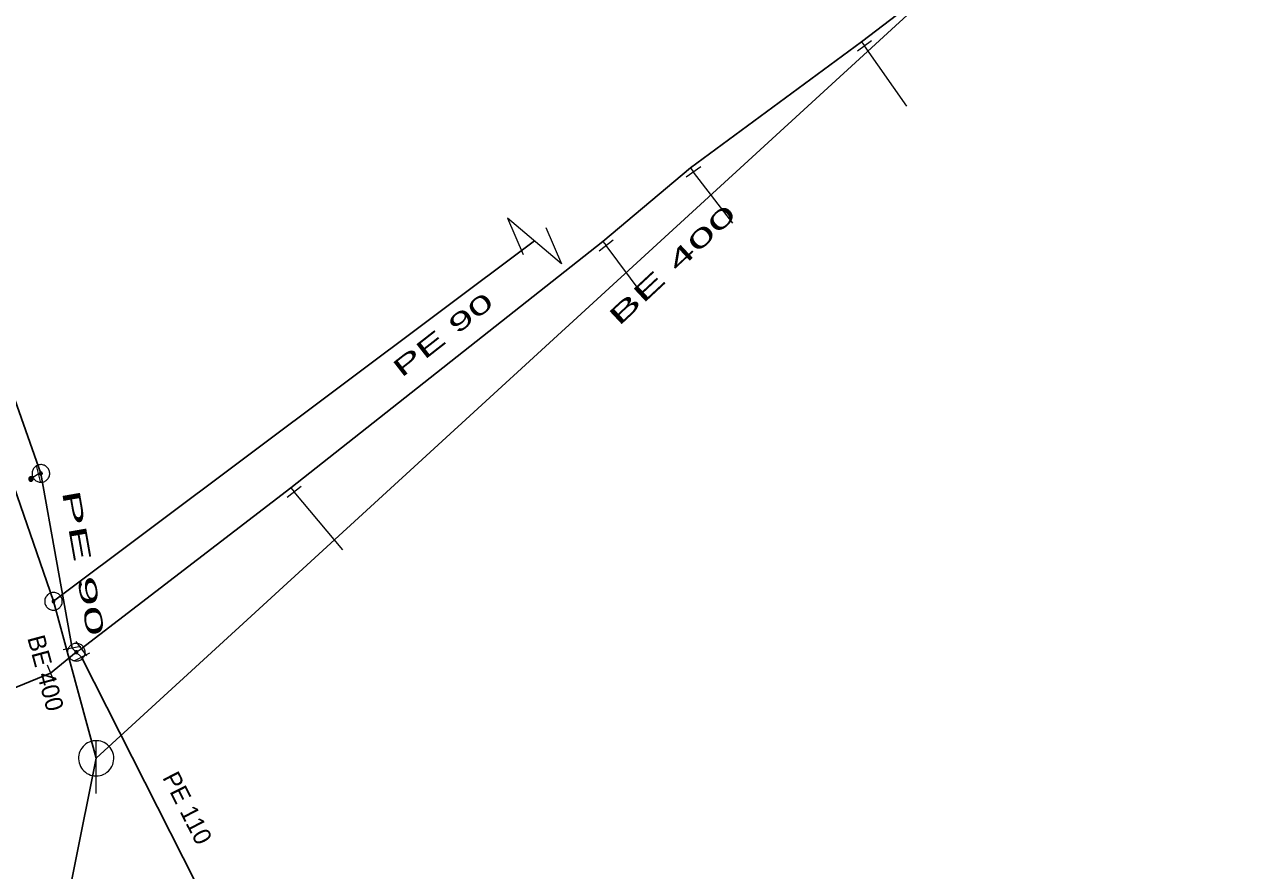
# Model space of a CAD drawing. Extents: x -779496 to -779026, y -977086 to -976624.
# Drawn here: x -779435.1 to -779365.5, y -977014.1 to -976966.2 of the extents above; entities that cross this region are included whole.
import ezdxf

# ---------------------------------------------------------------- set-up
doc = ezdxf.new("R2010")
doc.units = 0
doc.header["$LTSCALE"] = 0.4
doc.linetypes.add('MEDIUM_DASHED', pattern=[4.5, 3, -1.5])
for name, color, linetype, lineweight in [('1', 7, 'MEDIUM_DASHED', 25), ('13', 7, 'Continuous', 13), ('14', 7, 'Continuous', 13), ('17', 7, 'Continuous', 25), ('22', 7, 'Continuous', 13), ('31', 7, 'Continuous', 13), ('34', 7, 'Continuous', 13), ('47', 7, 'Continuous', 13), ('9', 7, 'Continuous', 13)]:
    doc.layers.add(name, color=color, linetype=linetype, lineweight=lineweight)

msp = doc.modelspace()

# ---------------------------------------------------------------- linework, layer by layer
at = {"layer": '13'}
for p, q in [((-779385.116, -976970.776), (-779387.52, -976967.366)), ((-779394.986, -976977.408), (-779397.208, -976974.51)), ((-779400.116, -976981.414), (-779402.155, -976978.679)), ((-779417.083, -976995.903), (-779419.831, -976992.633))]:
    msp.add_line(p, q, dxfattribs=at)
at = {"layer": '14', "lineweight": 25}
for p, q in [((-779370.105, -976951.862), (-779431.048, -977007.721)), ((-779406.215, -976978.414), (-779433.467, -976998.827))]:
    msp.add_line(p, q, dxfattribs=at)
at = {"layer": '14'}
for p, q in [((-779387.699, -976967.124), (-779387.52, -976967.366)), ((-779397.383, -976974.263), (-779397.208, -976974.51)), ((-779402.342, -976978.442), (-779402.155, -976978.679)), ((-779434.328, -976991.62), (-779434.743, -976991.897)), ((-779434.181, -976991.585), (-779434.328, -976991.62)), ((-779420.017, -976992.39), (-779419.831, -976992.633)), ((-779432.419, -977001.481), (-779432.174, -977001.71)), ((-779432.174, -977001.71), (-779431.903, -977001.512)), ((-779432.174, -977001.71), (-779431.872, -977001.993))]:
    msp.add_line(p, q, dxfattribs=at)
at = {"layer": '14', "lineweight": 25}
for points in [[(-779436.28, -976990.67), (-779433.467, -976998.827), (-779431.048, -977007.721)], [(-779431.048, -977007.721), (-779433.53, -977020.039), (-779409.204, -977061.045)]]:
    msp.add_lwpolyline(points, dxfattribs=at)
at = {"layer": '17'}
for p, q in [((-779434.181, -976991.585), (-779432.419, -977001.481)), ((-779432.174, -977001.71), (-779433.636, -977002.894))]:
    msp.add_line(p, q, dxfattribs=at)
for points in [[(-779454.175, -976923.809), (-779450.772, -976938.068), (-779448.031, -976948.717), (-779444.473, -976962.508), (-779436.901, -976983.894), (-779434.181, -976991.585)], [(-779433.636, -977002.894), (-779441.438, -977006.098), (-779447.947, -976991.515), (-779454.579, -976971.633), (-779460.072, -976955.085), (-779464.768, -976941.099)], [(-779431.903, -977001.512), (-779420.017, -976992.39), (-779402.342, -976978.442), (-779397.383, -976974.263), (-779387.699, -976967.124), (-779382.057, -976962.824), (-779375.728, -976957.945), (-779374.629, -976957.155), (-779365.489, -976951.461)], [(-779431.872, -977001.993), (-779421.818, -977021.866), (-779420.403, -977025.364), (-779413.614, -977038.243), (-779404.897, -977052.484), (-779402.2, -977057.302)]]:
    msp.add_lwpolyline(points, dxfattribs=at)
at = {"layer": '22'}
msp.add_line((-779431.048, -977009.721), (-779431.047, -977006.721), dxfattribs=at)
msp.add_lwpolyline([(-779430.048, -977007.721), (-779430.053, -977007.612), (-779430.071, -977007.504), (-779430.101, -977007.398), (-779430.141, -977007.297), (-779430.193, -977007.2), (-779430.255, -977007.11), (-779430.327, -977007.027), (-779430.407, -977006.953), (-779430.495, -977006.887), (-779430.589, -977006.832), (-779430.689, -977006.787), (-779430.794, -977006.754), (-779430.901, -977006.732), (-779431.01, -977006.722), (-779431.12, -977006.724), (-779431.228, -977006.738), (-779431.335, -977006.763), (-779431.438, -977006.8), (-779431.536, -977006.849), (-779431.628, -977006.907), (-779431.714, -977006.976), (-779431.791, -977007.053), (-779431.86, -977007.139), (-779431.919, -977007.231), (-779431.967, -977007.329), (-779432.004, -977007.432), (-779432.03, -977007.539), (-779432.044, -977007.647), (-779432.047, -977007.757), (-779432.037, -977007.866), (-779432.016, -977007.973), (-779431.982, -977008.077), (-779431.938, -977008.177), (-779431.883, -977008.272), (-779431.817, -977008.36), (-779431.743, -977008.44), (-779431.66, -977008.512), (-779431.57, -977008.574), (-779431.474, -977008.626), (-779431.372, -977008.667), (-779431.267, -977008.697), (-779431.159, -977008.715), (-779431.049, -977008.721), (-779430.94, -977008.715), (-779430.832, -977008.697), (-779430.727, -977008.668), (-779430.625, -977008.627), (-779430.528, -977008.575), (-779430.438, -977008.513), (-779430.355, -977008.442), (-779430.28, -977008.362), (-779430.215, -977008.274), (-779430.159, -977008.18), (-779430.115, -977008.08), (-779430.081, -977007.976), (-779430.059, -977007.868), (-779430.049, -977007.759)], close=True, dxfattribs=at)
at = {"layer": '31'}
msp.add_lwpolyline([(-779405.568, -976977.65), (-779404.689, -976979.706), (-779407.741, -976977.12), (-779406.861, -976979.176)], dxfattribs=at)
for points in [[(-779433.292, -976999.295), (-779433.244, -976999.274), (-779433.198, -976999.248), (-779433.156, -976999.218), (-779433.117, -976999.184), (-779433.081, -976999.145), (-779433.05, -976999.102), (-779433.024, -976999.058), (-779433.002, -976999.01), (-779432.985, -976998.961), (-779432.973, -976998.91), (-779432.967, -976998.857), (-779432.968, -976998.805), (-779432.972, -976998.753), (-779432.983, -976998.702), (-779432.998, -976998.652), (-779433.019, -976998.604), (-779433.045, -976998.558), (-779433.075, -976998.515), (-779433.109, -976998.477), (-779433.148, -976998.441), (-779433.191, -976998.41), (-779433.236, -976998.383), (-779433.283, -976998.361), (-779433.332, -976998.344), (-779433.383, -976998.333), (-779433.436, -976998.327), (-779433.488, -976998.327), (-779433.54, -976998.332), (-779433.591, -976998.343), (-779433.641, -976998.358), (-779433.689, -976998.379), (-779433.735, -976998.405), (-779433.778, -976998.435), (-779433.816, -976998.469), (-779433.852, -976998.508), (-779433.883, -976998.55), (-779433.91, -976998.595), (-779433.932, -976998.642), (-779433.949, -976998.692), (-779433.96, -976998.743), (-779433.966, -976998.796), (-779433.967, -976998.847), (-779433.961, -976998.9), (-779433.95, -976998.951), (-779433.935, -976999.001), (-779433.914, -976999.049), (-779433.888, -976999.095), (-779433.859, -976999.137), (-779433.824, -976999.176), (-779433.785, -976999.212), (-779433.743, -976999.243), (-779433.699, -976999.269), (-779433.651, -976999.291), (-779433.601, -976999.308), (-779433.55, -976999.32), (-779433.497, -976999.326), (-779433.446, -976999.326), (-779433.393, -976999.321), (-779433.342, -976999.31)], [(-779433.438, -976998.903), (-779433.429, -976998.9), (-779433.423, -976998.896), (-779433.416, -976998.891), (-779433.409, -976998.885), (-779433.403, -976998.879), (-779433.398, -976998.872), (-779433.394, -976998.864), (-779433.39, -976998.857), (-779433.388, -976998.848), (-779433.386, -976998.84), (-779433.385, -976998.831), (-779433.385, -976998.823), (-779433.386, -976998.815), (-779433.387, -976998.806), (-779433.39, -976998.798), (-779433.393, -976998.789), (-779433.397, -976998.783), (-779433.402, -976998.776), (-779433.408, -976998.769), (-779433.414, -976998.763), (-779433.421, -976998.758), (-779433.429, -976998.754), (-779433.436, -976998.75), (-779433.445, -976998.747), (-779433.453, -976998.746), (-779433.462, -976998.745), (-779433.47, -976998.745), (-779433.478, -976998.746), (-779433.487, -976998.747), (-779433.495, -976998.75), (-779433.504, -976998.753), (-779433.51, -976998.757), (-779433.517, -976998.762), (-779433.524, -976998.768), (-779433.53, -976998.774), (-779433.535, -976998.78), (-779433.539, -976998.789), (-779433.543, -976998.796), (-779433.546, -976998.805), (-779433.547, -976998.813), (-779433.548, -976998.822), (-779433.548, -976998.83), (-779433.547, -976998.838), (-779433.546, -976998.847), (-779433.543, -976998.855), (-779433.54, -976998.864), (-779433.536, -976998.87), (-779433.531, -976998.877), (-779433.525, -976998.884), (-779433.519, -976998.89), (-779433.513, -976998.895), (-779433.504, -976998.899), (-779433.497, -976998.903), (-779433.488, -976998.905), (-779433.48, -976998.907), (-779433.471, -976998.908), (-779433.463, -976998.908), (-779433.455, -976998.907), (-779433.446, -976998.906)]]:
    msp.add_lwpolyline(points, close=True, dxfattribs=at)
at = {"layer": '34'}
for p, q in [((-779387.117, -976967.069), (-779387.923, -976967.661)), ((-779396.798, -976974.222), (-779397.617, -976974.796)), ((-779401.762, -976978.368), (-779402.547, -976978.988)), ((-779434.444, -976991.133), (-779434.212, -976992.106)), ((-779419.435, -976992.327), (-779420.227, -976992.937)), ((-779431.926, -977001.392), (-779432.911, -977001.568)), ((-779432.199, -977001.109), (-779431.607, -977001.915)), ((-779431.426, -977001.766), (-779432.318, -977002.218)), ((-779433.826, -977002.431), (-779433.446, -977003.356))]:
    msp.add_line(p, q, dxfattribs=at)
at = {"layer": '47'}
for points in [[(-779434.065, -976992.071), (-779434.015, -976992.056), (-779433.966, -976992.036), (-779433.921, -976992.011), (-779433.877, -976991.982), (-779433.837, -976991.948), (-779433.801, -976991.909), (-779433.77, -976991.868), (-779433.742, -976991.823), (-779433.719, -976991.777), (-779433.701, -976991.727), (-779433.689, -976991.676), (-779433.683, -976991.624), (-779433.681, -976991.572), (-779433.685, -976991.52), (-779433.694, -976991.469), (-779433.709, -976991.419), (-779433.729, -976991.37), (-779433.754, -976991.324), (-779433.783, -976991.281), (-779433.817, -976991.241), (-779433.856, -976991.205), (-779433.897, -976991.173), (-779433.942, -976991.145), (-779433.988, -976991.122), (-779434.038, -976991.105), (-779434.089, -976991.093), (-779434.141, -976991.086), (-779434.193, -976991.085), (-779434.245, -976991.089), (-779434.296, -976991.098), (-779434.346, -976991.113), (-779434.395, -976991.133), (-779434.442, -976991.157), (-779434.484, -976991.187), (-779434.524, -976991.221), (-779434.56, -976991.259), (-779434.593, -976991.3), (-779434.62, -976991.345), (-779434.643, -976991.392), (-779434.66, -976991.442), (-779434.672, -976991.493), (-779434.679, -976991.544), (-779434.68, -976991.597), (-779434.676, -976991.649), (-779434.667, -976991.7), (-779434.652, -976991.75), (-779434.632, -976991.799), (-779434.608, -976991.845), (-779434.578, -976991.888), (-779434.544, -976991.928), (-779434.506, -976991.964), (-779434.465, -976991.996), (-779434.42, -976992.023), (-779434.373, -976992.046), (-779434.323, -976992.064), (-779434.272, -976992.076), (-779434.221, -976992.082), (-779434.168, -976992.084), (-779434.116, -976992.08)], [(-779434.161, -976991.664), (-779434.153, -976991.662), (-779434.145, -976991.658), (-779434.138, -976991.655), (-779434.131, -976991.65), (-779434.124, -976991.644), (-779434.119, -976991.638), (-779434.113, -976991.631), (-779434.108, -976991.624), (-779434.105, -976991.616), (-779434.102, -976991.608), (-779434.1, -976991.599), (-779434.099, -976991.591), (-779434.099, -976991.582), (-779434.099, -976991.574), (-779434.101, -976991.565), (-779434.103, -976991.557), (-779434.107, -976991.549), (-779434.11, -976991.542), (-779434.115, -976991.535), (-779434.121, -976991.528), (-779434.127, -976991.523), (-779434.134, -976991.517), (-779434.141, -976991.512), (-779434.149, -976991.508), (-779434.157, -976991.506), (-779434.166, -976991.504), (-779434.174, -976991.503), (-779434.183, -976991.503), (-779434.191, -976991.503), (-779434.2, -976991.505), (-779434.208, -976991.507), (-779434.216, -976991.511), (-779434.223, -976991.514), (-779434.23, -976991.519), (-779434.237, -976991.525), (-779434.243, -976991.53), (-779434.248, -976991.538), (-779434.253, -976991.545), (-779434.257, -976991.553), (-779434.259, -976991.561), (-779434.261, -976991.57), (-779434.262, -976991.578), (-779434.262, -976991.587), (-779434.262, -976991.595), (-779434.26, -976991.604), (-779434.258, -976991.612), (-779434.254, -976991.62), (-779434.251, -976991.627), (-779434.246, -976991.634), (-779434.24, -976991.641), (-779434.235, -976991.647), (-779434.227, -976991.652), (-779434.22, -976991.657), (-779434.212, -976991.66), (-779434.204, -976991.663), (-779434.195, -976991.665), (-779434.187, -976991.666), (-779434.178, -976991.666), (-779434.17, -976991.666)], [(-779432.058, -977002.196), (-779432.008, -977002.181), (-779431.959, -977002.161), (-779431.914, -977002.136), (-779431.87, -977002.107), (-779431.83, -977002.073), (-779431.794, -977002.034), (-779431.763, -977001.993), (-779431.735, -977001.948), (-779431.712, -977001.902), (-779431.694, -977001.852), (-779431.682, -977001.801), (-779431.676, -977001.749), (-779431.674, -977001.697), (-779431.678, -977001.645), (-779431.687, -977001.594), (-779431.702, -977001.544), (-779431.722, -977001.495), (-779431.747, -977001.449), (-779431.776, -977001.406), (-779431.81, -977001.366), (-779431.849, -977001.33), (-779431.89, -977001.298), (-779431.935, -977001.27), (-779431.981, -977001.247), (-779432.031, -977001.23), (-779432.082, -977001.218), (-779432.134, -977001.211), (-779432.186, -977001.21), (-779432.238, -977001.214), (-779432.289, -977001.223), (-779432.339, -977001.238), (-779432.388, -977001.258), (-779432.435, -977001.282), (-779432.477, -977001.312), (-779432.517, -977001.346), (-779432.553, -977001.384), (-779432.586, -977001.425), (-779432.613, -977001.47), (-779432.636, -977001.517), (-779432.653, -977001.567), (-779432.665, -977001.618), (-779432.672, -977001.669), (-779432.673, -977001.722), (-779432.669, -977001.774), (-779432.66, -977001.825), (-779432.645, -977001.875), (-779432.625, -977001.924), (-779432.601, -977001.97), (-779432.571, -977002.013), (-779432.537, -977002.053), (-779432.499, -977002.089), (-779432.458, -977002.121), (-779432.413, -977002.148), (-779432.366, -977002.171), (-779432.316, -977002.189), (-779432.265, -977002.201), (-779432.214, -977002.207), (-779432.161, -977002.209), (-779432.109, -977002.205)], [(-779432.154, -977001.789), (-779432.146, -977001.787), (-779432.138, -977001.783), (-779432.131, -977001.78), (-779432.124, -977001.775), (-779432.117, -977001.769), (-779432.112, -977001.763), (-779432.106, -977001.756), (-779432.101, -977001.749), (-779432.098, -977001.741), (-779432.095, -977001.733), (-779432.093, -977001.724), (-779432.092, -977001.716), (-779432.092, -977001.707), (-779432.092, -977001.699), (-779432.094, -977001.69), (-779432.096, -977001.682), (-779432.1, -977001.674), (-779432.103, -977001.667), (-779432.108, -977001.66), (-779432.114, -977001.653), (-779432.12, -977001.648), (-779432.127, -977001.642), (-779432.134, -977001.637), (-779432.142, -977001.633), (-779432.15, -977001.631), (-779432.159, -977001.629), (-779432.167, -977001.628), (-779432.176, -977001.628), (-779432.184, -977001.628), (-779432.193, -977001.63), (-779432.201, -977001.632), (-779432.209, -977001.636), (-779432.216, -977001.639), (-779432.223, -977001.644), (-779432.23, -977001.65), (-779432.236, -977001.655), (-779432.241, -977001.663), (-779432.246, -977001.67), (-779432.25, -977001.678), (-779432.252, -977001.686), (-779432.254, -977001.695), (-779432.255, -977001.703), (-779432.255, -977001.712), (-779432.255, -977001.72), (-779432.253, -977001.729), (-779432.251, -977001.737), (-779432.247, -977001.745), (-779432.244, -977001.752), (-779432.239, -977001.759), (-779432.233, -977001.766), (-779432.228, -977001.772), (-779432.22, -977001.777), (-779432.213, -977001.782), (-779432.205, -977001.785), (-779432.197, -977001.788), (-779432.188, -977001.79), (-779432.18, -977001.791), (-779432.171, -977001.791), (-779432.163, -977001.791)]]:
    msp.add_lwpolyline(points, close=True, dxfattribs=at)
at = {"layer": '9'}
for points in [[(-779434.869, -976991.897), (-779434.869, -976991.91), (-779434.867, -976991.923), (-779434.864, -976991.936), (-779434.859, -976991.948), (-779434.853, -976991.96), (-779434.846, -976991.971), (-779434.838, -976991.981), (-779434.828, -976991.991), (-779434.818, -976991.999), (-779434.807, -976992.006), (-779434.795, -976992.012), (-779434.783, -976992.017), (-779434.77, -976992.02), (-779434.757, -976992.022), (-779434.744, -976992.024), (-779434.731, -976992.023), (-779434.718, -976992.021), (-779434.705, -976992.018), (-779434.693, -976992.013), (-779434.681, -976992.007), (-779434.67, -976992), (-779434.66, -976991.992), (-779434.65, -976991.982), (-779434.642, -976991.972), (-779434.635, -976991.961), (-779434.629, -976991.949), (-779434.624, -976991.937), (-779434.621, -976991.924), (-779434.619, -976991.911), (-779434.617, -976991.898), (-779434.618, -976991.885), (-779434.62, -976991.872), (-779434.623, -976991.859), (-779434.628, -976991.847), (-779434.634, -976991.835), (-779434.641, -976991.824), (-779434.649, -976991.814), (-779434.659, -976991.804), (-779434.669, -976991.796), (-779434.68, -976991.789), (-779434.692, -976991.783), (-779434.704, -976991.778), (-779434.717, -976991.775), (-779434.73, -976991.773), (-779434.743, -976991.772), (-779434.756, -976991.772), (-779434.769, -976991.774), (-779434.782, -976991.777), (-779434.794, -976991.782), (-779434.806, -976991.788), (-779434.817, -976991.795), (-779434.827, -976991.803), (-779434.837, -976991.813), (-779434.845, -976991.823), (-779434.852, -976991.834), (-779434.858, -976991.846), (-779434.863, -976991.858), (-779434.866, -976991.871), (-779434.868, -976991.884)], [(-779434.849, -976991.897), (-779434.85, -976991.908), (-779434.848, -976991.919), (-779434.845, -976991.93), (-779434.841, -976991.94), (-779434.836, -976991.95), (-779434.83, -976991.959), (-779434.823, -976991.968), (-779434.815, -976991.976), (-779434.806, -976991.983), (-779434.797, -976991.989), (-779434.787, -976991.994), (-779434.777, -976991.998), (-779434.766, -976992.001), (-779434.755, -976992.004), (-779434.744, -976992.004), (-779434.733, -976992.004), (-779434.722, -976992.002), (-779434.711, -976991.999), (-779434.701, -976991.995), (-779434.691, -976991.99), (-779434.682, -976991.984), (-779434.673, -976991.977), (-779434.665, -976991.969), (-779434.658, -976991.96), (-779434.652, -976991.951), (-779434.647, -976991.941), (-779434.643, -976991.931), (-779434.64, -976991.92), (-779434.638, -976991.909), (-779434.637, -976991.898), (-779434.637, -976991.887), (-779434.639, -976991.876), (-779434.642, -976991.865), (-779434.646, -976991.855), (-779434.651, -976991.845), (-779434.657, -976991.836), (-779434.664, -976991.827), (-779434.672, -976991.819), (-779434.681, -976991.812), (-779434.69, -976991.806), (-779434.7, -976991.801), (-779434.71, -976991.797), (-779434.721, -976991.794), (-779434.732, -976991.792), (-779434.743, -976991.792), (-779434.754, -976991.791), (-779434.765, -976991.793), (-779434.776, -976991.796), (-779434.786, -976991.8), (-779434.796, -976991.805), (-779434.805, -976991.811), (-779434.814, -976991.818), (-779434.822, -976991.826), (-779434.829, -976991.835), (-779434.835, -976991.844), (-779434.84, -976991.854), (-779434.844, -976991.864), (-779434.847, -976991.875), (-779434.849, -976991.886)], [(-779434.83, -976991.897), (-779434.83, -976991.906), (-779434.829, -976991.915), (-779434.826, -976991.924), (-779434.823, -976991.932), (-779434.819, -976991.94), (-779434.814, -976991.948), (-779434.808, -976991.955), (-779434.802, -976991.961), (-779434.795, -976991.967), (-779434.787, -976991.972), (-779434.779, -976991.976), (-779434.771, -976991.979), (-779434.762, -976991.982), (-779434.753, -976991.983), (-779434.744, -976991.985), (-779434.735, -976991.984), (-779434.726, -976991.983), (-779434.717, -976991.98), (-779434.709, -976991.977), (-779434.701, -976991.973), (-779434.693, -976991.968), (-779434.686, -976991.962), (-779434.68, -976991.956), (-779434.674, -976991.949), (-779434.669, -976991.941), (-779434.665, -976991.933), (-779434.662, -976991.925), (-779434.659, -976991.916), (-779434.658, -976991.907), (-779434.656, -976991.898), (-779434.657, -976991.889), (-779434.658, -976991.88), (-779434.661, -976991.871), (-779434.664, -976991.863), (-779434.668, -976991.855), (-779434.673, -976991.847), (-779434.679, -976991.84), (-779434.685, -976991.834), (-779434.692, -976991.828), (-779434.7, -976991.823), (-779434.708, -976991.819), (-779434.716, -976991.816), (-779434.725, -976991.813), (-779434.734, -976991.812), (-779434.743, -976991.811), (-779434.752, -976991.811), (-779434.761, -976991.812), (-779434.77, -976991.815), (-779434.778, -976991.818), (-779434.786, -976991.822), (-779434.794, -976991.827), (-779434.801, -976991.833), (-779434.807, -976991.839), (-779434.813, -976991.846), (-779434.818, -976991.854), (-779434.822, -976991.862), (-779434.825, -976991.87), (-779434.828, -976991.879), (-779434.829, -976991.888)], [(-779434.81, -976991.897), (-779434.81, -976991.904), (-779434.809, -976991.911), (-779434.808, -976991.918), (-779434.805, -976991.924), (-779434.802, -976991.93), (-779434.798, -976991.936), (-779434.794, -976991.942), (-779434.789, -976991.947), (-779434.783, -976991.951), (-779434.777, -976991.955), (-779434.771, -976991.958), (-779434.765, -976991.961), (-779434.758, -976991.962), (-779434.751, -976991.965), (-779434.744, -976991.965), (-779434.737, -976991.965), (-779434.73, -976991.963), (-779434.723, -976991.962), (-779434.717, -976991.959), (-779434.71, -976991.956), (-779434.705, -976991.952), (-779434.699, -976991.948), (-779434.694, -976991.943), (-779434.69, -976991.937), (-779434.686, -976991.931), (-779434.683, -976991.925), (-779434.68, -976991.919), (-779434.678, -976991.912), (-779434.677, -976991.905), (-779434.676, -976991.898), (-779434.676, -976991.891), (-779434.677, -976991.884), (-779434.679, -976991.877), (-779434.682, -976991.871), (-779434.685, -976991.864), (-779434.689, -976991.859), (-779434.693, -976991.853), (-779434.698, -976991.848), (-779434.704, -976991.844), (-779434.709, -976991.84), (-779434.716, -976991.837), (-779434.722, -976991.834), (-779434.729, -976991.832), (-779434.736, -976991.831), (-779434.743, -976991.831), (-779434.75, -976991.831), (-779434.757, -976991.831), (-779434.764, -976991.833), (-779434.77, -976991.836), (-779434.776, -976991.839), (-779434.782, -976991.843), (-779434.788, -976991.847), (-779434.793, -976991.852), (-779434.797, -976991.858), (-779434.801, -976991.863), (-779434.804, -976991.87), (-779434.807, -976991.876), (-779434.808, -976991.883), (-779434.81, -976991.89)], [(-779434.79, -976991.897), (-779434.79, -976991.902), (-779434.79, -976991.907), (-779434.789, -976991.912), (-779434.787, -976991.916), (-779434.785, -976991.921), (-779434.782, -976991.925), (-779434.779, -976991.928), (-779434.775, -976991.932), (-779434.772, -976991.935), (-779434.768, -976991.938), (-779434.763, -976991.94), (-779434.759, -976991.942), (-779434.754, -976991.943), (-779434.749, -976991.945), (-779434.744, -976991.945), (-779434.739, -976991.945), (-779434.734, -976991.944), (-779434.729, -976991.943), (-779434.725, -976991.941), (-779434.72, -976991.939), (-779434.716, -976991.936), (-779434.712, -976991.933), (-779434.709, -976991.929), (-779434.706, -976991.926), (-779434.703, -976991.922), (-779434.701, -976991.917), (-779434.699, -976991.913), (-779434.698, -976991.908), (-779434.697, -976991.903), (-779434.696, -976991.898), (-779434.696, -976991.893), (-779434.697, -976991.888), (-779434.698, -976991.883), (-779434.7, -976991.879), (-779434.702, -976991.874), (-779434.705, -976991.87), (-779434.708, -976991.866), (-779434.711, -976991.863), (-779434.715, -976991.86), (-779434.719, -976991.857), (-779434.724, -976991.855), (-779434.728, -976991.853), (-779434.733, -976991.852), (-779434.738, -976991.851), (-779434.743, -976991.851), (-779434.748, -976991.851), (-779434.753, -976991.852), (-779434.758, -976991.852), (-779434.762, -976991.854), (-779434.767, -976991.856), (-779434.771, -976991.859), (-779434.774, -976991.862), (-779434.778, -976991.865), (-779434.781, -976991.869), (-779434.784, -976991.873), (-779434.786, -976991.878), (-779434.788, -976991.882), (-779434.789, -976991.887), (-779434.79, -976991.892)], [(-779434.77, -976991.897), (-779434.77, -976991.9), (-779434.771, -976991.903), (-779434.77, -976991.905), (-779434.769, -976991.908), (-779434.768, -976991.911), (-779434.766, -976991.913), (-779434.764, -976991.915), (-779434.762, -976991.917), (-779434.76, -976991.919), (-779434.758, -976991.921), (-779434.755, -976991.923), (-779434.752, -976991.924), (-779434.75, -976991.924), (-779434.747, -976991.925), (-779434.744, -976991.925), (-779434.741, -976991.925), (-779434.738, -976991.925), (-779434.735, -976991.924), (-779434.733, -976991.923), (-779434.73, -976991.922), (-779434.728, -976991.92), (-779434.725, -976991.918), (-779434.723, -976991.916), (-779434.722, -976991.914), (-779434.72, -976991.912), (-779434.719, -976991.909), (-779434.717, -976991.906), (-779434.717, -976991.904), (-779434.716, -976991.901), (-779434.715, -976991.898), (-779434.716, -976991.895), (-779434.716, -976991.892), (-779434.717, -976991.889), (-779434.718, -976991.887), (-779434.719, -976991.884), (-779434.721, -976991.882), (-779434.722, -976991.879), (-779434.724, -976991.877), (-779434.727, -976991.876), (-779434.729, -976991.874), (-779434.732, -976991.873), (-779434.734, -976991.872), (-779434.737, -976991.871), (-779434.74, -976991.871), (-779434.743, -976991.87), (-779434.746, -976991.871), (-779434.749, -976991.87), (-779434.751, -976991.872), (-779434.754, -976991.872), (-779434.757, -976991.873), (-779434.759, -976991.875), (-779434.761, -976991.876), (-779434.763, -976991.878), (-779434.765, -976991.881), (-779434.767, -976991.883), (-779434.768, -976991.886), (-779434.769, -976991.888), (-779434.77, -976991.891), (-779434.77, -976991.894)], [(-779434.751, -976991.897), (-779434.751, -976991.899), (-779434.751, -976991.899), (-779434.75, -976991.899), (-779434.75, -976991.901), (-779434.751, -976991.902), (-779434.749, -976991.902), (-779434.749, -976991.902), (-779434.749, -976991.904), (-779434.749, -976991.904), (-779434.748, -976991.905), (-779434.746, -976991.905), (-779434.746, -976991.905), (-779434.746, -976991.906), (-779434.744, -976991.906), (-779434.744, -976991.906), (-779434.743, -976991.906), (-779434.742, -976991.906), (-779434.742, -976991.905), (-779434.741, -976991.905), (-779434.739, -976991.905), (-779434.739, -976991.904), (-779434.739, -976991.904), (-779434.738, -976991.903), (-779434.738, -976991.903), (-779434.736, -976991.902), (-779434.736, -976991.901), (-779434.735, -976991.9), (-779434.735, -976991.9), (-779434.735, -976991.899), (-779434.735, -976991.898), (-779434.735, -976991.897), (-779434.735, -976991.896), (-779434.735, -976991.896), (-779434.736, -976991.895), (-779434.736, -976991.894), (-779434.737, -976991.893), (-779434.737, -976991.893), (-779434.738, -976991.892), (-779434.738, -976991.892), (-779434.739, -976991.891), (-779434.74, -976991.891), (-779434.741, -976991.89), (-779434.741, -976991.89), (-779434.742, -976991.89), (-779434.743, -976991.89), (-779434.744, -976991.89), (-779434.745, -976991.89), (-779434.745, -976991.89), (-779434.746, -976991.891), (-779434.747, -976991.89), (-779434.748, -976991.892), (-779434.748, -976991.892), (-779434.749, -976991.892), (-779434.749, -976991.892), (-779434.75, -976991.894), (-779434.75, -976991.895), (-779434.75, -976991.896), (-779434.751, -976991.896), (-779434.751, -976991.897)]]:
    msp.add_lwpolyline(points, close=True, dxfattribs=at)

# ---------------------------------------------------------------- texts
at = {"layer": '1'}
for s, rotation, width, p in [('BE 400', 43, 2.1, (-779401.446, -976983.281)), ('PE 90 ', 38, 1.85, (-779413.752, -976986.19)), ('PE 90 ', 280, 2.3, (-779432.997, -976992.609))]:
    msp.add_text(s, height=1, rotation=rotation, dxfattribs=dict(at, width=width)).set_placement(p)
for s, rotation, p in [('BE 400', 285, (-779434.96, -977000.899)), ('PE 110', 297, (-779427.32, -977008.807))]:
    msp.add_text(s, height=1, rotation=rotation, dxfattribs=at).set_placement(p)

doc.saveas('drawing.dxf')
